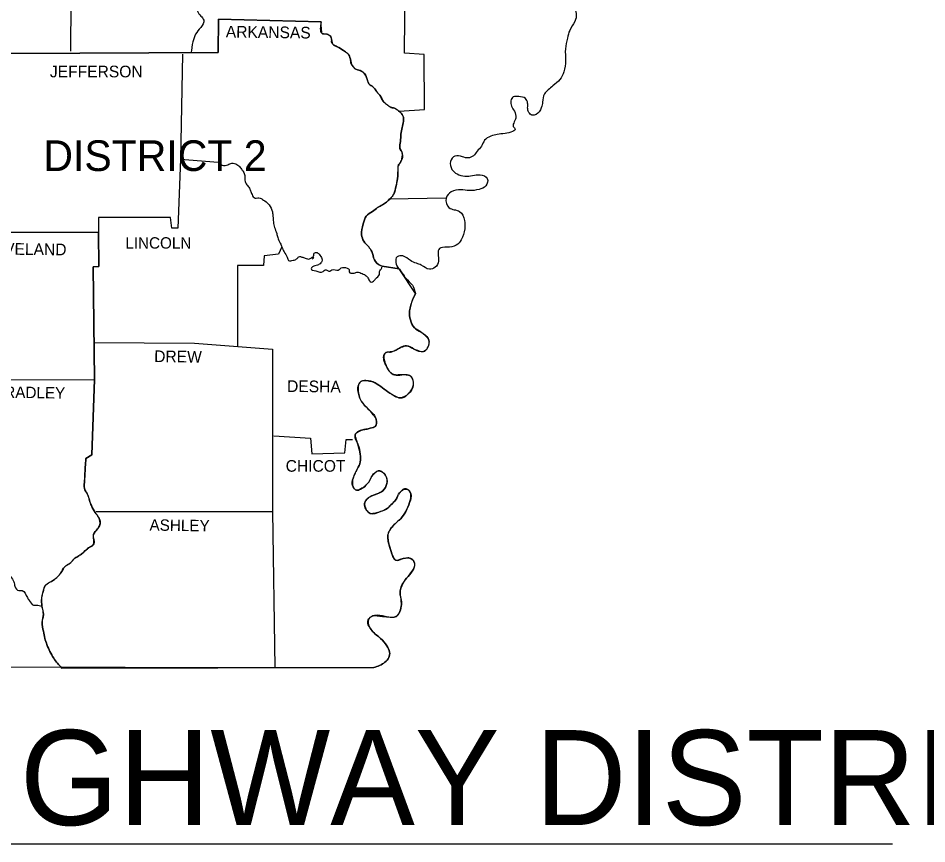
# Model space of a CAD drawing. Extents: x -33639 to 34530, y -17264 to 5867.
# Drawn here: x 2998 to 4841, y 2539 to 4213 of the extents above; entities that cross this region are included whole.
import ezdxf

# ---------------------------------------------------------------- set-up
doc = ezdxf.new("R2010")
doc.units = 0
for name, color, linetype in [('1', 7, 'Continuous'), ('2', 7, 'Continuous'), ('3', 7, 'Continuous'), ('S_MISC_BOUNDARY', 7, 'Continuous')]:
    doc.layers.add(name, color=color, linetype=linetype)

msp = doc.modelspace()

# ---------------------------------------------------------------- linework, layer by layer
at = {"layer": '1'}
for p, q in [((3749.3, 3847.5), (3866.5, 3849.3)), ((1258, 2539.3), (4771.1, 2539.3))]:
    msp.add_line(p, q, dxfattribs=at)
for points in [[(3039.4, 4582.2), (3071.3, 4580), (3071.8, 4369.8), (3043.2, 4250.4), (3104.3, 4247.6), (3103.8, 4146.3)], [(3770.2, 4024.7), (3822, 4028), (3821.4, 4139.7), (3781.2, 4142.5), (3783.4, 4361), (3748.8, 4365.9), (3747.7, 4512.9), (4219.8, 4516.2)], [(3331, 4140.3), (3326.6, 3927.3), (3403.1, 3921.2)], [(3326.6, 3927.3), (3321.7, 3787.5), (3309, 3787.5), (3306.8, 3809), (3160.4, 3809), (3160.4, 3778.2)], [(3532.5, 3749.5), (3525.9, 3734.7), (3496.7, 3731.9), (3495.1, 3712.1), (3442.8, 3712.1), (3442.2, 3547.6)], [(3594.1, 3725.3), (3595.8, 3727), (3597.4, 3728.6), (3597.4, 3728.6)], [(3151.1, 3555.8), (3355.3, 3554.2), (3513.8, 3542.1)], [(3513.8, 3542.1), (3513.8, 3212.9), (3518.2, 2896.5)], [(2904, 3480.4), (3152.7, 3481)], [(3516.5, 3366.5), (3590.3, 3362.1), (3593.6, 3330.2), (3660.2, 3332.4), (3662.9, 3359.3), (3675.6, 3359.3)], [(1700.9, 3345), (1702, 2899.8), (3719, 2896.5)], [(3156, 3213.5), (3513.8, 3213.5)]]:
    msp.add_lwpolyline(points, dxfattribs=at)
for points in [[(4182.4, 4383), (4169.8, 4367), (4151.1, 4376.9), (4151.1, 4390.1), (4153.8, 4403.9), (4147.2, 4412.7), (4135.7, 4408.9), (4135.7, 4391.8), (4134.6, 4375.3), (4131.3, 4351.6), (4139, 4344.5), (4156.6, 4342.3), (4169.2, 4339), (4176.9, 4326.3), (4176.4, 4310.9), (4170.3, 4296), (4161.5, 4283.9), (4147.8, 4279.5), (4136.8, 4286.7), (4132.4, 4301), (4127.4, 4313.6), (4118.1, 4323), (4108.1, 4312.5), (4105.9, 4293.3), (4106.5, 4276.8), (4106.5, 4254.2), (4120.8, 4239.3), (4129.6, 4222.3), (4126.9, 4206.9), (4116.4, 4188.7), (4112, 4172.8), (4107.6, 4151.3), (4108.1, 4127.6), (4104.3, 4104.5), (4096.6, 4089.1), (4082.3, 4076.4), (4072.9, 4068.2), (4065.2, 4059.9), (4061.4, 4043.4), (4058.6, 4031.9), (4048.2, 4018.1), (4039.9, 4017), (4033.3, 4022.5), (4031.1, 4031.9), (4031.1, 4041.2), (4026.7, 4050.6), (4012.9, 4054.4), (4001.9, 4053.9), (3997, 4046.2), (4004.1, 4024.7), (4006.9, 4011), (4003, 3992.2), (4005.2, 3990), (3985.4, 3979.6), (3969.5, 3977.9), (3956.3, 3974.1), (3943.6, 3965.8), (3937.5, 3953.7), (3928.7, 3943.8), (3921, 3934.5), (3910.6, 3930.1), (3899, 3932.3), (3883.6, 3933.9), (3874.8, 3922.9), (3877.6, 3906.9), (3888, 3897.6), (3903.4, 3893.2), (3919.4, 3894.3), (3934.8, 3895.9), (3949.1, 3888.2), (3946.3, 3873.4), (3932.6, 3866.2), (3912.2, 3864), (3895.7, 3865.7), (3875.9, 3861.3), (3866, 3848.6), (3871.5, 3829.3), (3893, 3821.6), (3902.9, 3803.5), (3903.4, 3786.4), (3896.3, 3763.8), (3886.4, 3753.4), (3867.1, 3749), (3852.2, 3746.2), (3850, 3720.9), (3843.4, 3708.3), (3831.9, 3704.4), (3815.4, 3712.7), (3805.5, 3716.5), (3793.3, 3722), (3777.9, 3731.4), (3766.4, 3729.7), (3769.7, 3705.5), (3770.8, 3704.4), (3784, 3686.2), (3797.2, 3671.9), (3803.3, 3654.9)], [(3336, 4296), (3349.8, 4286.7), (3364.1, 4275.7), (3367.9, 4260.8), (3366.8, 4250.4), (3362.4, 4241.6), (3361.3, 4227.8), (3367.9, 4217.9), (3374, 4209.6), (3367.9, 4194.8), (3357.5, 4181), (3352, 4165.6), (3348.1, 4142.5)], [(3403.1, 3921.2), (3411.4, 3915.7), (3423, 3916.3), (3430.7, 3919.6), (3436.7, 3919), (3445, 3914.1), (3450.5, 3907.5), (3454.3, 3902.5), (3457.1, 3894.8), (3457.1, 3887.7), (3459.8, 3877.8), (3463.1, 3873.9), (3467.5, 3866.8), (3470.3, 3860.2), (3471.9, 3855.8), (3478, 3848.6), (3483.5, 3849.1), (3488.5, 3848.6), (3495.1, 3844.7), (3505, 3837), (3506.6, 3834.8), (3513.2, 3820.5), (3514.3, 3811.7), (3515.4, 3800.2), (3517.6, 3789.2), (3522, 3777.1), (3524.2, 3768.8), (3529.2, 3757.2), (3532.5, 3749.5), (3536.9, 3739.6), (3543.5, 3728.6), (3546.2, 3722), (3555.6, 3722.6), (3562.2, 3725.3), (3567.2, 3729.7), (3573.2, 3729.2), (3579.8, 3727), (3588.6, 3725.3), (3594.1, 3728.6), (3596.9, 3730.8), (3597.4, 3735.8), (3602.4, 3738.5), (3607.9, 3734.7), (3613.9, 3725.9), (3613.9, 3720.4), (3611.7, 3717.1), (3604.6, 3712.7), (3594.7, 3709.4), (3591.9, 3705.5), (3601.3, 3701.1), (3616.1, 3700), (3620, 3703.3), (3629.9, 3700.6), (3633.7, 3703.3), (3647, 3702.8), (3653, 3707.2), (3665.1, 3706.6), (3669, 3703.9), (3669, 3698.9), (3678.9, 3696.7), (3686, 3698.4), (3695.4, 3695.6), (3703.6, 3691.2), (3708, 3685.1), (3713.5, 3678.5), (3718.5, 3680.2), (3722.4, 3685.1), (3730.6, 3693.9), (3730.6, 3699.5), (3732.8, 3703.3), (3735.6, 3708.8)], [(3803.3, 3654.9), (3797.7, 3642.2), (3791.7, 3620.2), (3793.3, 3601.5), (3801.6, 3585.5), (3814.8, 3576.7), (3829.1, 3564.1), (3828, 3544.8), (3819.8, 3537.6), (3800.5, 3542.6), (3785.6, 3549.2), (3773, 3545.4), (3755.9, 3537.1), (3743.3, 3535.4), (3743.8, 3509), (3760.9, 3490.3), (3775.7, 3490.3), (3792.8, 3488.1), (3798.9, 3468.3), (3788.9, 3451.8), (3772.4, 3443.5), (3751.5, 3453.4), (3736.7, 3463.9), (3721.8, 3473.8), (3703.1, 3478.8), (3692.6, 3476.6), (3687.7, 3453.4), (3696.5, 3432.5), (3710.8, 3418.2), (3724, 3399.5), (3721.8, 3385.8), (3711.9, 3381.9), (3694.3, 3378), (3683.8, 3372.5), (3681.1, 3368.1), (3686.6, 3349.4), (3691.5, 3329.1), (3691.5, 3313.7), (3685.5, 3299.3), (3676.1, 3277.3), (3677.2, 3263), (3683.8, 3256.4), (3692.1, 3258.6), (3703.1, 3266.3), (3710.2, 3275.1), (3716.3, 3286.1), (3727.9, 3295.5), (3742.2, 3287.2), (3745.5, 3270.2), (3737.2, 3255.3), (3725.7, 3248.7), (3711.3, 3243.2), (3700.9, 3231.1), (3703.6, 3216.8), (3711.9, 3209.1), (3732.3, 3212.9), (3746, 3219), (3753.7, 3226.7), (3763.1, 3236.1), (3768, 3245.4), (3775.2, 3255.3), (3787.8, 3258.1), (3793.9, 3249.8), (3791.7, 3231.1), (3784, 3213.5), (3773.5, 3198.6), (3762, 3188.2), (3747.7, 3165.6), (3750.4, 3144.7), (3755.9, 3127.6), (3763.6, 3114.4), (3776.8, 3117.2), (3791.7, 3118.8), (3800.5, 3111.7), (3799.4, 3096.3), (3788.4, 3081.4), (3777.9, 3067.1), (3772.4, 3047.3), (3774.6, 3033.5), (3774.6, 3020.9), (3770.2, 3007.1), (3762.5, 2999.4), (3742.2, 3000), (3720.7, 3002.2), (3709.1, 2995.6), (3711.3, 2976.8), (3724, 2963.1), (3732.8, 2955.9), (3745.5, 2940.5), (3751, 2927.9), (3749.3, 2916.8), (3741.6, 2907.5), (3719, 2896.5)], [(2586.4, 3193.1), (2595.2, 3199.2), (2603.5, 3202.5), (2611.7, 3200.8), (2620.5, 3199.7), (2628.2, 3200.8), (2638.2, 3199.2), (2646.4, 3194.2), (2655.8, 3190.4), (2665.1, 3190.4), (2673.4, 3190.4), (2680.5, 3185.4), (2693.7, 3186), (2704.7, 3190.4), (2715.8, 3193.7), (2730.6, 3195.3), (2743.8, 3186), (2753.2, 3178.3), (2760.9, 3169.5), (2766.4, 3159.6), (2772.4, 3154.1), (2782.3, 3150.2), (2790.1, 3148.5), (2799.4, 3145.8), (2804.4, 3143.6), (2808.8, 3133.1), (2815.9, 3118.8), (2829.7, 3113.9), (2846.7, 3120.5), (2860.5, 3124.3), (2870.4, 3127.6), (2876.5, 3129.8), (2882, 3130.4), (2880.3, 3131.5), (2886.9, 3133.1), (2893, 3128.7), (2896.8, 3122.7), (2903.4, 3113.9), (2909.5, 3106.2), (2915.5, 3103.4), (2921.6, 3106.7), (2929.8, 3104), (2937, 3101.2), (2945.3, 3099), (2952.4, 3098.5), (2961.8, 3096.3), (2968.9, 3092.4), (2975.5, 3088.6), (2982.1, 3081.4), (2988.7, 3070.4), (2990.9, 3061.6), (2998.6, 3052.8), (3005.8, 3052.8), (3016.2, 3038.5), (3020.1, 3033), (3028.4, 3023.1), (3034.4, 3023.1), (3046, 3020.9)]]:
    msp.add_spline(points, degree=3, dxfattribs=at)
at = {"layer": 'S_MISC_BOUNDARY'}
for p, q in [((3736.1, 3710.5), (3770.2, 3705)), ((3770.2, 3705), (3736.1, 3710.5)), ((3803.3, 3654.9), (3770.2, 3705)), ((3086.1, 2895.4), (3719, 2896.5))]:
    msp.add_line(p, q, dxfattribs=at)
for points in [[(2654.1, 3851.9), (2653.6, 3926.7), (2658.5, 3925.1), (2665.1, 4069.3), (2695.9, 4073.7), (2698.1, 4092.4), (2716.3, 4095.7), (2717.4, 4106.7), (2845.6, 4110.6), (2850.6, 4144.1), (2982.1, 4141.9), (3403.1, 4143.6), (3404.2, 4211.3), (3612.3, 4205.8)], [(3612.3, 4205.8), (3404.2, 4211.3), (3403.1, 4143.6), (2982.1, 4141.9), (2850.6, 4144.1), (2845.6, 4110.6), (2717.4, 4106.7), (2716.3, 4095.7), (2698.1, 4092.4), (2695.9, 4073.7), (2665.1, 4069.3), (2658.5, 3925.1), (2653.6, 3926.7), (2654.1, 3851.9), (2760.9, 3848.6)], [(3135.1, 3320.3), (3147.2, 3328), (3152.7, 3481), (3149.4, 3709.4), (3161, 3709.9), (3160.4, 3778.7), (3159.3, 3778.7), (2964.5, 3779.8), (2884.2, 3774.9)], [(2884.2, 3774.9), (2964.5, 3779.8), (3159.3, 3778.7), (3160.4, 3778.7), (3161, 3709.9), (3149.4, 3709.4), (3152.7, 3481), (3147.2, 3328), (3135.1, 3320.3)]]:
    msp.add_lwpolyline(points, dxfattribs=at)
for points in [[(3612.3, 4205.8), (3613.9, 4183.2), (3627.1, 4179.9), (3632.6, 4173.9), (3635.4, 4161.2), (3644.8, 4155.7), (3657.4, 4148), (3665.1, 4142.5), (3670.6, 4133.7), (3673.9, 4119.4), (3682.7, 4110), (3694.8, 4105.6), (3703.6, 4095.2), (3709.1, 4080.3), (3717.9, 4073.7), (3726.8, 4062.1), (3731.2, 4057.2), (3738.9, 4044), (3746.6, 4037.4), (3752.1, 4033.5), (3760.9, 4030.8), (3771.9, 4023.6), (3779, 4012.6), (3779, 4004.3), (3776.3, 3991.7), (3774.1, 3978.5), (3773, 3963.6), (3771.9, 3950.4), (3776.8, 3939.4), (3774.1, 3922.9), (3768.6, 3914.1), (3768, 3902), (3766.4, 3883.8), (3764.2, 3873.4), (3759.2, 3856.3), (3752.1, 3847.5)], [(3740.3, 4042.5), (3738.9, 4044), (3736.6, 4047.1), (3734.9, 4050.5), (3733.2, 4054), (3731.2, 4057.2), (3726.8, 4062.1), (3724.5, 4065), (3722.3, 4067.9), (3720.2, 4070.8), (3717.9, 4073.7), (3715.9, 4075.5), (3713.5, 4077), (3711.2, 4078.5), (3709.1, 4080.3), (3707.3, 4083.7), (3706.2, 4087.6), (3705.2, 4091.5), (3703.6, 4095.2), (3694.8, 4105.6), (3692, 4107.1), (3688.8, 4107.9), (3685.7, 4108.6), (3682.7, 4110), (3680.1, 4112), (3677.7, 4114.2), (3673.9, 4119.4), (3672.7, 4122.9), (3672.2, 4126.5), (3671.7, 4130.2), (3670.6, 4133.7), (3669.5, 4136.1), (3668.3, 4138.4), (3666.9, 4140.6), (3665.1, 4142.5), (3663.2, 4144), (3661.3, 4145.4), (3657.4, 4148), (3644.8, 4155.7), (3635.4, 4161.2), (3633.7, 4163.6), (3633.5, 4167), (3633.5, 4170.6), (3632.6, 4173.9), (3627.1, 4179.9), (3625.6, 4180.7), (3623.7, 4181), (3619.5, 4180.9), (3615.9, 4181.2), (3614.6, 4181.9), (3613.9, 4183.2), (3613.5, 4186), (3613.1, 4188.8), (3612.6, 4194.5), (3612.3, 4205.8)], [(3752.1, 3847.5), (3756.1, 3851.6), (3759.2, 3856.3), (3760.1, 3858.4), (3760.8, 3860.5), (3762.1, 3864.8), (3764.2, 3873.4), (3766.4, 3883.8), (3768, 3902), (3768.2, 3905), (3768.3, 3908), (3768.4, 3911.1), (3768.6, 3914.1), (3769.4, 3916.5), (3771, 3918.6), (3772.7, 3920.6), (3774.1, 3922.9), (3776.4, 3931.2), (3776.9, 3935.4), (3776.8, 3939.4), (3775.9, 3942.2), (3774.1, 3944.8), (3772.5, 3947.5), (3771.9, 3950.4), (3773, 3963.6), (3774.1, 3978.5), (3776.3, 3991.7), (3779, 4004.3), (3779.5, 4008.5), (3779, 4012.6), (3778, 4015.7), (3776.4, 4018.5), (3771.9, 4023.6), (3766.6, 4027.7), (3760.9, 4030.8), (3758.7, 4031.5), (3756.4, 4032), (3754.2, 4032.6), (3752.1, 4033.5), (3746.6, 4037.4), (3740.3, 4042.5)], [(3752.1, 3847.5), (3736.7, 3834.8), (3726.8, 3829.3), (3716.3, 3821.6), (3703.6, 3812.3), (3697.6, 3796.3), (3694.3, 3774.3), (3698.7, 3761.1), (3708.6, 3749.5), (3715.2, 3740.2), (3720.1, 3723.7), (3732.3, 3712.1), (3736.1, 3710.5)], [(3736.1, 3710.5), (3732.3, 3712.1), (3720.1, 3723.7), (3715.2, 3740.2), (3708.6, 3749.5), (3698.7, 3761.1), (3694.3, 3774.3), (3697.6, 3796.3), (3703.6, 3812.3), (3716.3, 3821.6), (3726.8, 3829.3), (3736.7, 3834.8), (3752.1, 3847.5)], [(3803.3, 3654.9), (3797.7, 3642.2), (3791.7, 3620.2), (3793.3, 3601.5), (3801.6, 3585.5), (3814.8, 3576.7), (3829.1, 3564.1), (3828, 3544.8), (3819.8, 3537.6), (3800.5, 3542.6), (3785.6, 3549.2), (3773, 3545.4), (3755.9, 3537.1), (3743.3, 3535.4), (3743.8, 3509), (3760.9, 3490.3), (3775.7, 3490.3), (3792.8, 3488.1), (3798.9, 3468.3), (3788.9, 3451.8), (3772.4, 3443.5), (3751.5, 3453.4), (3736.7, 3463.9), (3721.8, 3473.8), (3703.1, 3478.8), (3692.6, 3476.6), (3687.7, 3453.4), (3696.5, 3432.5), (3710.8, 3418.2), (3724, 3399.5), (3721.8, 3385.8), (3711.9, 3381.9), (3694.3, 3378), (3683.8, 3372.5), (3681.1, 3368.1), (3686.6, 3349.4), (3691.5, 3329.1), (3691.5, 3313.7), (3685.5, 3299.3), (3676.1, 3277.3), (3677.2, 3263), (3683.8, 3256.4), (3692.1, 3258.6), (3703.1, 3266.3), (3710.2, 3275.1), (3716.3, 3286.1), (3727.9, 3295.5), (3742.2, 3287.2), (3745.5, 3270.2), (3737.2, 3255.3), (3725.7, 3248.7), (3711.3, 3243.2), (3700.9, 3231.1), (3703.6, 3216.8), (3711.9, 3209.1), (3732.3, 3212.9), (3746, 3219), (3753.7, 3226.7), (3763.1, 3236.1), (3768, 3245.4), (3775.2, 3255.3), (3787.8, 3258.1), (3793.9, 3249.8), (3791.7, 3231.1), (3784, 3213.5), (3773.5, 3198.6), (3762, 3188.2), (3747.7, 3165.6), (3750.4, 3144.7), (3755.9, 3127.6), (3763.6, 3114.4), (3776.8, 3117.2), (3791.7, 3118.8), (3800.5, 3111.7), (3799.4, 3096.3), (3788.4, 3081.4), (3777.9, 3067.1), (3772.4, 3047.3), (3774.6, 3033.5), (3774.6, 3020.9), (3770.2, 3007.1), (3762.5, 2999.4), (3742.2, 3000), (3720.7, 3002.2), (3709.1, 2995.6), (3711.3, 2976.8), (3724, 2963.1), (3732.8, 2955.9), (3745.5, 2940.5), (3751, 2927.9), (3749.3, 2916.8), (3741.6, 2907.5), (3719, 2896.5)], [(3700.6, 3428), (3696.5, 3432.5), (3690.8, 3442.7), (3687.7, 3453.4), (3686.7, 3459.2), (3686.7, 3465.1), (3688.4, 3471), (3692.6, 3476.6), (3693.9, 3477.6), (3695.2, 3478.3), (3697.9, 3479), (3703.1, 3478.8), (3707.8, 3478.1), (3712.6, 3477.3), (3721.8, 3473.8), (3736.7, 3463.9), (3751.5, 3453.4), (3761.9, 3447.4), (3772.4, 3443.5), (3780.7, 3445.3), (3788.9, 3451.8), (3792.7, 3455.8), (3795.5, 3459.9), (3798.9, 3468.3), (3799.5, 3473.4), (3799, 3479), (3796.8, 3484.2), (3792.8, 3488.1), (3790.7, 3489.2), (3788.6, 3489.9), (3784.3, 3490.4), (3775.7, 3490.3), (3772, 3490.3), (3768.3, 3490), (3764.6, 3489.9), (3760.9, 3490.3), (3757.9, 3491.4), (3755.3, 3493.1), (3750.8, 3497.7), (3743.8, 3509), (3742.2, 3512.1), (3739, 3523.1), (3739.5, 3530.2), (3740.9, 3533.1), (3743.3, 3535.4), (3744.7, 3536.2), (3746.3, 3536.5), (3749.5, 3536.6), (3752.8, 3536.5), (3755.9, 3537.1), (3760.2, 3539.1), (3764.4, 3541.2), (3768.6, 3543.4), (3773, 3545.4), (3779.3, 3548), (3785.6, 3549.2), (3787.5, 3548.9), (3789.4, 3548.3), (3793.1, 3546.5), (3796.8, 3544.4), (3800.5, 3542.6), (3810.1, 3539.2), (3819.8, 3537.6), (3824.4, 3540), (3826.3, 3542.3), (3828, 3544.8), (3830.4, 3549.6), (3831.6, 3554.8), (3831.3, 3559.9), (3829.1, 3564.1), (3822.3, 3570.7), (3814.8, 3576.7), (3811.5, 3578.9), (3808.1, 3580.9), (3804.8, 3583), (3801.6, 3585.5), (3793.3, 3601.5), (3791.7, 3620.2), (3794.3, 3631.3), (3797.7, 3642.2), (3799.1, 3645.4), (3800.7, 3648.6), (3802.2, 3651.7), (3803.3, 3654.9)], [(3793.8, 3250.2), (3791.6, 3254.6), (3789.8, 3256.5), (3787.8, 3258.1), (3784.7, 3259.1), (3781.3, 3258.9), (3777.9, 3257.5), (3775.2, 3255.3), (3771.4, 3250.5), (3768, 3245.4), (3766.8, 3243), (3765.8, 3240.5), (3763.1, 3236.1), (3753.7, 3226.7), (3746, 3219), (3732.3, 3212.9), (3722.1, 3209.7), (3716.9, 3208.8), (3711.9, 3209.1), (3707.3, 3211.9), (3703.6, 3216.8), (3700.5, 3224), (3700.9, 3231.1), (3702.7, 3234.6), (3705, 3237.9), (3711.3, 3243.2), (3714.9, 3244.9), (3718.5, 3246.1), (3722.1, 3247.3), (3725.7, 3248.7), (3737.2, 3255.3), (3745.5, 3270.2), (3746.2, 3274.3), (3746, 3278.7), (3744.8, 3283), (3742.2, 3287.2), (3738.7, 3290.9), (3735, 3293.8), (3727.9, 3295.5), (3721.8, 3291.9), (3716.3, 3286.1), (3714.5, 3283.4), (3713.1, 3280.6), (3711.8, 3277.8), (3710.2, 3275.1), (3703.1, 3266.3), (3692.1, 3258.6), (3688, 3256.7), (3683.8, 3256.4), (3680, 3258.9), (3677.2, 3263), (3675.8, 3266.6), (3675.1, 3270.3), (3675.2, 3273.9), (3676.1, 3277.3), (3685.5, 3299.3), (3691.5, 3313.7), (3691.5, 3329.1), (3686.6, 3349.4), (3685.2, 3354.1), (3683.7, 3358.8), (3682.2, 3363.5), (3681.1, 3368.1), (3681.8, 3370.5), (3682.7, 3371.6), (3683.8, 3372.5), (3694.3, 3378), (3698.7, 3379.2), (3703.1, 3380), (3707.5, 3380.9), (3711.9, 3381.9), (3717, 3383.3), (3719.4, 3384.3), (3721.8, 3385.8), (3724, 3399.5), (3718, 3409.1), (3710.8, 3418.2), (3705.8, 3423.2), (3700.6, 3428)], [(3086.1, 2895.4), (3069.6, 2915.7), (3061.9, 2929), (3055.9, 2943.3), (3051.5, 2955.9), (3048.7, 2970.2), (3046, 2988.4), (3048.7, 3004.9), (3046.5, 3018.1), (3044.9, 3033), (3048.7, 3053.3), (3053.7, 3064.3), (3065.2, 3071.5), (3073.5, 3077), (3083.4, 3087.5), (3092.2, 3101.2), (3104.3, 3109.5), (3112.6, 3118.3), (3120.3, 3123.2), (3127.4, 3128.2), (3140.1, 3139.2), (3150, 3145.8), (3150.5, 3166.7), (3158.8, 3178.3), (3163.2, 3186), (3161, 3200.8), (3153.8, 3211.3), (3146.1, 3225), (3142.3, 3235.5), (3138.4, 3247.6), (3131.8, 3260.3), (3131.8, 3271.8), (3132.9, 3287.2), (3133.5, 3303.2), (3135.1, 3320.3)], [(3135.1, 3320.3), (3133.5, 3303.2), (3132.9, 3287.2), (3131.8, 3271.8), (3131.5, 3266), (3131.8, 3260.3), (3132.2, 3258.6), (3132.9, 3256.9), (3134.8, 3253.9), (3136.9, 3250.8), (3138.4, 3247.6), (3142.3, 3235.5), (3146.1, 3225), (3153.8, 3211.3), (3155.5, 3208.6), (3157.4, 3206.1), (3159.2, 3203.5), (3161, 3200.8), (3163.8, 3193.5), (3164, 3189.6), (3163.2, 3186), (3158.8, 3178.3), (3156.8, 3175.3), (3154.6, 3172.5), (3152.5, 3169.6), (3150.5, 3166.7), (3149.6, 3161.7), (3150.8, 3155.9), (3151.7, 3150.3), (3150, 3145.8), (3147.6, 3143.9), (3145.1, 3142.4), (3142.5, 3140.9), (3140.1, 3139.2), (3136.9, 3136.4), (3133.8, 3133.6), (3130.7, 3130.8), (3127.4, 3128.2), (3120.3, 3123.2), (3112.6, 3118.3), (3110.3, 3116.3), (3108.3, 3114), (3106.4, 3111.7), (3104.3, 3109.5), (3102, 3107.7)], [(3719, 2896.5), (3741.6, 2907.5), (3749.3, 2916.8), (3751, 2927.9), (3745.5, 2940.5), (3732.8, 2955.9), (3724, 2963.1), (3711.3, 2976.8), (3707.2, 2986), (3707.1, 2991.1), (3709.1, 2995.6), (3711.6, 2998.2), (3714.4, 3000.3), (3720.7, 3002.2), (3726.1, 3001.8), (3731.4, 3001.2), (3736.8, 3000.5), (3742.2, 3000), (3752.3, 2999.1), (3762.5, 2999.4), (3767, 3002.2), (3768.8, 3004.5), (3770.2, 3007.1), (3774.6, 3020.9), (3774.6, 3033.5), (3774.2, 3037), (3773.5, 3040.4), (3772.8, 3043.8), (3772.4, 3047.3), (3772.7, 3052.4), (3773.6, 3057.6), (3777.9, 3067.1), (3788.4, 3081.4), (3799.4, 3096.3), (3802.1, 3103.7), (3800.5, 3111.7), (3798.8, 3114.2), (3796.8, 3116.5), (3791.7, 3118.8), (3784.3, 3118.4), (3776.8, 3117.2), (3773.5, 3116.2), (3770.2, 3115), (3766.9, 3114.1), (3763.6, 3114.4), (3762, 3115.3), (3760.6, 3116.6), (3758.7, 3119.9), (3755.9, 3127.6), (3750.4, 3144.7), (3747.9, 3155.2), (3747.7, 3165.6), (3748.5, 3168.8), (3749.7, 3171.8), (3753.1, 3177.6), (3762, 3188.2), (3764.8, 3190.9), (3767.9, 3193.4), (3770.8, 3195.9), (3773.5, 3198.6), (3784, 3213.5), (3791.7, 3231.1), (3794, 3240.4), (3793.9, 3249.8), (3793.8, 3250.2)], [(3102, 3107.7), (3096.9, 3104.7), (3094.4, 3103.1), (3092.2, 3101.2), (3091.5, 3100.5), (3090.9, 3099.7), (3089.7, 3098), (3087.7, 3094.4), (3085.7, 3090.8), (3083.4, 3087.5), (3081.1, 3084.7), (3078.8, 3081.9), (3073.5, 3077), (3065.2, 3071.5), (3062.3, 3069.7), (3059.4, 3068.1), (3056.5, 3066.3), (3053.7, 3064.3), (3051.7, 3062.1), (3050.4, 3059.4), (3049.5, 3056.4), (3048.7, 3053.3), (3047.3, 3048.3), (3045.9, 3043.2), (3044.9, 3033), (3046.5, 3018.1), (3048.7, 3004.9), (3048.5, 3000.8), (3047.3, 2996.7), (3046.2, 2992.5), (3046, 2988.4), (3048.7, 2970.2), (3051.5, 2955.9), (3055.9, 2943.3), (3061.9, 2929), (3069.6, 2915.7), (3086.1, 2895.4)]]:
    msp.add_spline(points, degree=3, dxfattribs=at)

# ---------------------------------------------------------------- texts
at = {"layer": '2'}
for s, height, rotation, p in [('ARKANSAS', 23.66, 359.2678, (3418.6, 4174.4)), ('CLEVELAND', 23.67, 359.3377, (2907.3, 3734.7)), ('DREW', 23.66, 359.2258, (3273.3, 3516.2)), ('BRADLEY', 23.11, 359.1449, (2948.6, 3444.1)), ('DESHA', 23.66, 359.3704, (3542.9, 3455.6)), ('ASHLEY', 23.11, 359.2361, (3263.9, 3174.4))]:
    msp.add_text(s, height=height, rotation=rotation, dxfattribs=at).set_placement(p)
for s, height, p in [('JEFFERSON', 23.67, (3061.9, 4093.5)), ('LINCOLN', 23.11, (3214.9, 3746.2)), ('CHICOT', 23.67, (3540.2, 3293.8)), ('ARKANSAS HIGHWAY DISTRICT 2', 192.623, (1269, 2577.3))]:
    msp.add_text(s, height=height, dxfattribs=at).set_placement(p)
at = {"layer": '3'}
msp.add_text('DISTRICT 2', height=62.19, dxfattribs=at).set_placement((3048.7, 3903.6))

doc.saveas('drawing.dxf')
